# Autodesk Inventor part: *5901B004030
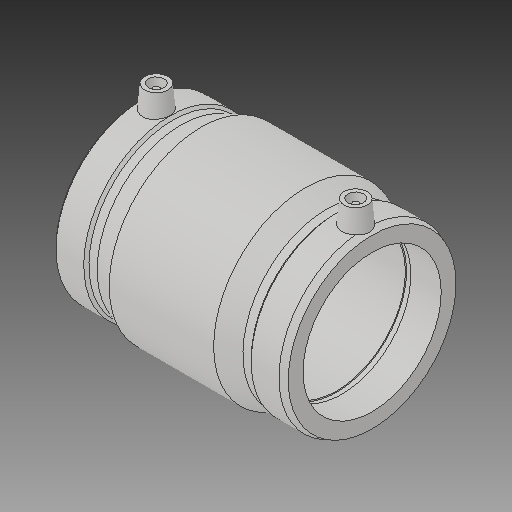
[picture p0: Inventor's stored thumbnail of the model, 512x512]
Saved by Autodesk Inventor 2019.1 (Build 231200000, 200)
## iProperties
Created: 2017-06
Part Number: *5901B004030
Material: Generic
Description: PLASSON IPS COUPLER 3''
Document SubType Name: Modeling
Designer: KIM
Mass: 8622.19 g
Surface Area: 6772.47 cm^2
Volume: 8622.19 cm^3
Density: 1 g/cm^3
Appearance: Default
Author: KIM
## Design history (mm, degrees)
derived "5901B.ipt"
feature "Solid1::5901B.ipt"
tag "TaggingFeature1"
body "Solid1"
other parameters: "d0" = 149.098, "d1" = 88.7, "d2" = 118.11, "d3" = 72.898, "d4" = 37.2745, "d5" = 106.299, "d6" = 70.96, "d7" = 88.7, "d8" = 168 deg, "d10" = 29.1592, "d11" = 9.71973, "d13" = 149.098, "d14" = 17.6296, "d18" = 88.7, "d19" = 3.52592, "d20" = 168 deg, "d22" = 111.0234, "d23" = 118.11, "d24" = 107.6927, "d25" = 135 deg, "d26" = 67.0941, "d27" = 135 deg, "d29" = 69.088, "d30" = 15, "d31" = 52.1843, "d34" = 5 deg, "d35" = 15, "d39" = 5 deg, "d41" = 4, "d42" = 14, "d43" = 0, "d45" = 4, "d46" = 14, "d47" = 0, "d48" = 3, "d49" = 0, "d50" = 3, "d51" = 0, "d52" = 21.14042, "d53" = 5.2851, "d55" = 72.898, "d_" = 88.7, "L_" = 149.098, "L_1" = 72.898, "D_" = 118.11, "A_" = 69.088, "d_2" = 12, "B_" = 69.088
